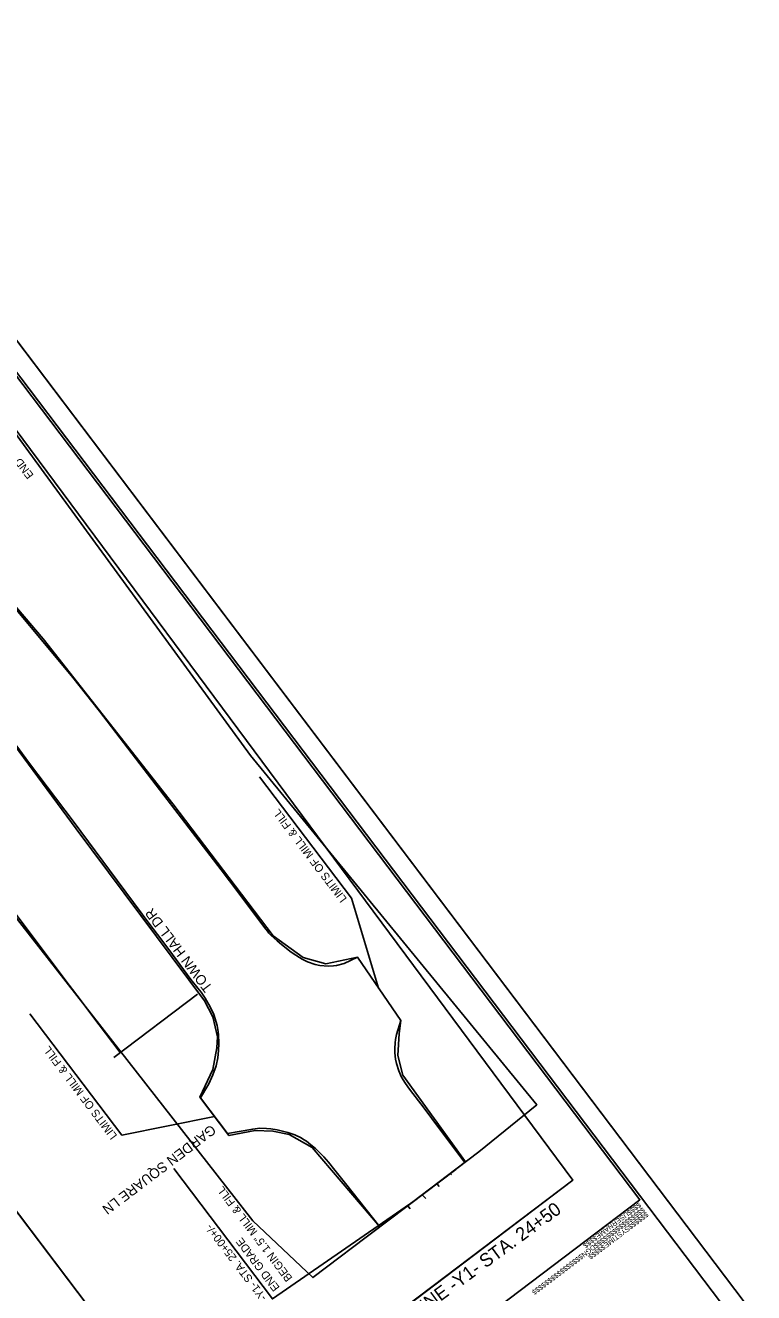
# Model space of a CAD drawing. Extents: x 2046295 to 2051060, y 758814 to 763808.
# Drawn here: x 2046974 to 2047429, y 759224 to 760015 of the extents above; entities that cross this region are included whole.
import ezdxf

# ---------------------------------------------------------------- set-up
doc = ezdxf.new("R2010")
doc.units = 0
for name, color, linetype in [('Matchline', 7, 'Continuous'), ('Matchline Text', 7, 'Continuous'), ('Prop Dimension', 7, 'Continuous'), ('Prop DSN Text', 7, 'Continuous'), ('Prop EOT', 7, 'Continuous'), ('Prop Lane Lines', 7, 'Continuous'), ('Scratch_Level_0', 7, 'Continuous'), ('Scratch_Level_3', 7, 'Continuous'), ('Sheet Block Revision CELL', 7, 'Continuous'), ('Sheet Clip Boundary CELL', 7, 'Continuous'), ('Sheet Cutting Line CELL', 7, 'Continuous'), ('Sheet Plan CELL', 7, 'Continuous'), ('Sheet Plot Border Inside CELL', 7, 'Continuous'), ('Sheet Plot Border Outside CELL', 7, 'Continuous')]:
    doc.layers.add(name, color=color, linetype=linetype)

msp = doc.modelspace()

# ---------------------------------------------------------------- linework, layer by layer
at = {"layer": 'Matchline'}
msp.add_line((2047173.57, 759186.27), (2047315.83, 759293.98), dxfattribs=at)
at = {"layer": 'Prop DSN Text'}
for p, q in [((2047001.09, 759415.7), (2046925.61, 759515.87)), ((2047001.03, 759415.78), (2047007.77, 759406.8)), ((2047028.85, 759370.67), (2047081.18, 759410.06))]:
    msp.add_line(p, q, dxfattribs=at)
for points in [[(2047120.01, 759545.99), (2047177.51, 759470.05), (2047194.36, 759413.92)], [(2047007.83, 759406.73), (2047015.1, 759397.08), (2047032.77, 759373.62)], [(2046976.46, 759397.92), (2047033.96, 759321.98), (2047091.89, 759333.7)], [(2047066.36, 759301.22), (2047128.02, 759219.77), (2047216.91, 759281.2)]]:
    msp.add_lwpolyline(points, dxfattribs=at)
msp.add_arc((2047056.2, 759443.17), 60.56, 216.90097, 216.98607, dxfattribs=at)
at = {"layer": 'Prop EOT'}
for p, q in [((2047181.15, 759433.17), (2047208.28, 759393.64)), ((2047083.1, 759345.32), (2047099.88, 759323.15))]:
    msp.add_line(p, q, dxfattribs=at)
for points in [[(2047095.91, 759487.83), (2047060.1, 759534.55), (2047037.66, 759563.83), (2047019.89, 759587.02), (2047003.2, 759607.99), (2046976.38, 759640.27), (2046961.44, 759658.24), (2046939.14, 759684.21), (2046899.4, 759728.85), (2046871.69, 759758.79), (2046844.06, 759788.42), (2046836.53, 759796.51), (2046823.09, 759810.56), (2046805.62, 759829.99), (2046780.45, 759856.59), (2046770.6, 759867.45), (2046758.76, 759880.49), (2046748.01, 759892.54), (2046735.95, 759905.24)], [(2047051.48, 759453.65), (2047026.19, 759487.57), (2047004.02, 759517.31), (2046975.49, 759555.05), (2046969.9, 759562.91), (2046958.31, 759578.45), (2046946.96, 759593.22), (2046930.3, 759614.91), (2046923.02, 759624.38), (2046916.39, 759632.65), (2046910.23, 759640.6), (2046901.22, 759651.47), (2046884.87, 759672.25), (2046869.65, 759691.35), (2046862.8, 759699.47), (2046849.9, 759714.08), (2046843.12, 759722.39), (2046829.52, 759739.07)], [(2047095.91, 759487.83), (2047101.19, 759480.91), (2047109.58, 759469.99), (2047114.98, 759462.58), (2047122.59, 759452.46), (2047123.14, 759451.76), (2047124.84, 759449.44), (2047125.77, 759448.28), (2047127.18, 759446.88), (2047130.9, 759443.42), (2047133.74, 759441.1), (2047136.69, 759438.82), (2047138.8, 759437.09), (2047140.89, 759435.59), (2047146.52, 759432.07), (2047150.01, 759430.43), (2047154.68, 759428.71), (2047157.72, 759428.05), (2047162.95, 759427.73), (2047166.09, 759427.81), (2047167.99, 759428.01), (2047172.88, 759429.36), (2047181.15, 759433.17)], [(2047083.1, 759345.32), (2047088.24, 759354.09), (2047089.16, 759355.98), (2047090.77, 759359.71), (2047092.79, 759365.41), (2047093.81, 759370.4), (2047094.32, 759374.97), (2047094.53, 759379.25), (2047094.36, 759384.85), (2047093.9, 759388.02), (2047093.45, 759390.6), (2047091.32, 759397.36), (2047089.05, 759402.27), (2047085.91, 759407.69), (2047083.4, 759411.41), (2047081.41, 759413.85), (2047077.06, 759419.21), (2047065.51, 759434.91), (2047058.21, 759444.65), (2047051.48, 759453.65)], [(2047248.23, 759304.91), (2047231.81, 759326.84), (2047222.79, 759338.82), (2047213.7, 759350.87), (2047211.19, 759354.25), (2047208.74, 759358.31), (2047207.05, 759362.19), (2047205.52, 759366.89), (2047204.94, 759369.43), (2047204.44, 759373.39), (2047204.41, 759376.12), (2047204.68, 759379.75), (2047205, 759381.78), (2047205.56, 759384.92), (2047208.28, 759393.64)], [(2047195.14, 759264.72), (2047173.73, 759291.85), (2047167.07, 759300.27), (2047163.01, 759305.24), (2047160.2, 759308.5), (2047157.73, 759311.06), (2047155.01, 759313.62), (2047152.06, 759316.04), (2047149.3, 759318.26), (2047147.5, 759319.31), (2047145.88, 759320.35), (2047142.1, 759322.15), (2047137.72, 759323.77), (2047134.23, 759324.62), (2047130.9, 759325.45), (2047126.93, 759326.01), (2047124.3, 759326.17), (2047120.15, 759326.31), (2047115.71, 759325.84), (2047099.88, 759323.15)]]:
    msp.add_lwpolyline(points, dxfattribs=at)
at = {"layer": 'Prop Lane Lines'}
for p, q in [((2047231.26, 759291.3), (2047230.69, 759291.91)), ((2047232.22, 759290.03), (2047231.26, 759291.3)), ((2047239.95, 759297.19), (2047239.13, 759298.16)), ((2047223.85, 759282.5), (2047221.51, 759284.81)), ((2047214.16, 759275.92), (2047212.66, 759277.98))]:
    msp.add_line(p, q, dxfattribs=at)
at = {"layer": 'Scratch_Level_0'}
for points in [[(2046843.22, 759930.29), (2047114.24, 759559.33), (2047293.25, 759341.06), (2047256.97, 759311.53), (2047189.95, 759260.79), (2047242.63, 759300.67), (2047213.75, 759278.81), (2047210.2, 759276.12), (2047205.1, 759272.26), (2047198.92, 759267.58), (2047195.14, 759264.72), (2047153.36, 759233.09), (2047115.74, 759268.55), (2046954.25, 759474.97)], [(2046930.3, 759614.91), (2047005.4, 759513.5), (2047085.66, 759406.06), (2047090.77, 759396.08), (2047093.77, 759383.45), (2047093.34, 759376.58), (2047090.73, 759362.99), (2047082.65, 759345.68), (2047100.83, 759321.77), (2047117.13, 759324.96), (2047128.32, 759324.58), (2047138.41, 759322.56), (2047152.89, 759314.29), (2047195.14, 759264.72), (2047209.73, 759275.77), (2047248.75, 759305.31), (2047209.51, 759359.45), (2047206.3, 759371.91), (2047207.24, 759385.49), (2047208.28, 759393.64), (2047181.15, 759433.17), (2047161.36, 759429.12), (2047147.15, 759433.15), (2047128.4, 759446.56), (2047065.81, 759528.99), (2046984.79, 759632.17), (2046929.97, 759696.38)]]:
    msp.add_lwpolyline(points, dxfattribs=at)
at = {"layer": 'Scratch_Level_3'}
msp.add_lwpolyline([(2046611.43, 759509.41), (2046530.13, 759447.86), (2046668.42, 759191.21), (2046850.67, 758939.32), (2046974.7, 759016.31), (2047093.77, 759108.41), (2046789, 759510.96), (2046715.54, 759607.98), (2046662.34, 759543.92)], close=True, dxfattribs=at)
at = {"layer": 'Sheet Block Revision CELL'}
msp.add_line((2047106.56, 759091.51), (2046563.3, 759809.07), dxfattribs=at)
at = {"layer": 'Sheet Clip Boundary CELL'}
msp.add_lwpolyline([(2046947.67, 758972.8), (2047186.85, 759153.88), (2047203.68, 759209.07), (2047315.83, 759293.98), (2046807.51, 759978.36), (2046429.78, 759650.86), (2046498.33, 759560.32), (2046397.16, 759483.72), (2046835.66, 758904.54)], close=True, dxfattribs=at)
at = {"layer": 'Sheet Cutting Line CELL'}
msp.add_line((2047428.76, 759210.16), (2046819.05, 760015.49), dxfattribs=at)
at = {"layer": 'Sheet Plan CELL'}
msp.add_line((2047357.69, 759281.65), (2047357.69, 759281.65), dxfattribs=at)
for points in [[(2046312.14, 759618.94), (2046855.41, 758901.37), (2047357.69, 759281.65), (2046814.43, 759999.2)], [(2047357.69, 759281.65), (2046855.43, 758901.37), (2046384.6, 759523.22), (2046456.38, 759577.58), (2046383.94, 759673.27), (2046814.43, 759999.2)]]:
    msp.add_lwpolyline(points, close=True, dxfattribs=at)
at = {"layer": 'Sheet Plot Border Inside CELL'}
msp.add_lwpolyline([(2047414.48, 759209.14), (2046811.11, 760006.08), (2046306.43, 759624), (2046909.81, 758827.05)], close=True, dxfattribs=at)
at = {"layer": 'Sheet Plot Border Outside CELL'}
msp.add_lwpolyline([(2047428.76, 759210.16), (2046819.05, 760015.49), (2046295.24, 759618.91), (2046904.95, 758813.59)], close=True, dxfattribs=at)

# ---------------------------------------------------------------- texts
at = {"layer": 'Matchline Text'}
msp.add_text('BREAKLINE -Y1- STA. 24+50', height=8.4, rotation=36.34241, dxfattribs=at).set_placement((2047188.28, 759185.02))
at = {"layer": 'Prop Dimension'}
for s, rotation, p in [('TOWN HALL DR', 127.12987, (2047090.86, 759414.36)), ('GARDEN SQUARE LN', 217.12987, (2047089.69, 759328.94))]:
    msp.add_text(s, height=6.225, rotation=rotation, dxfattribs=at).set_placement(p)
at = {"layer": 'Prop DSN Text'}
for s, p in [('END CONSTRUCTION', (2046979.05, 759734.47)), ('LIMITS OF MILL & FILL', (2047174.78, 759469.77)), ('LIMITS OF MILL & FILL', (2047031.23, 759321.69)), ('BEGIN 1.5" MILL & FILL', (2047140.76, 759232.85)), ('-Y1- STA. 25+00+/-', (2047124.82, 759220.78)), ('END GRADE', (2047132.79, 759226.82))]:
    msp.add_text(s, height=5, rotation=127.12988, dxfattribs=at).set_placement(p)
at = {"layer": 'Sheet Plan CELL'}
for s, p in [('$$$$$$$$$$$$$$$$DGN$$$$$$$$$$$$$$$$', (2047359.33, 759277.14)), ('$$$$USERNAME$$$$', (2047356.95, 759280.27)), ('$$$$$$SYSTIME$$$$$', (2047361.54, 759274.24))]:
    msp.add_text(s, height=3.15, rotation=217.12944, dxfattribs=at).set_placement(p)

doc.saveas('drawing.dxf')
